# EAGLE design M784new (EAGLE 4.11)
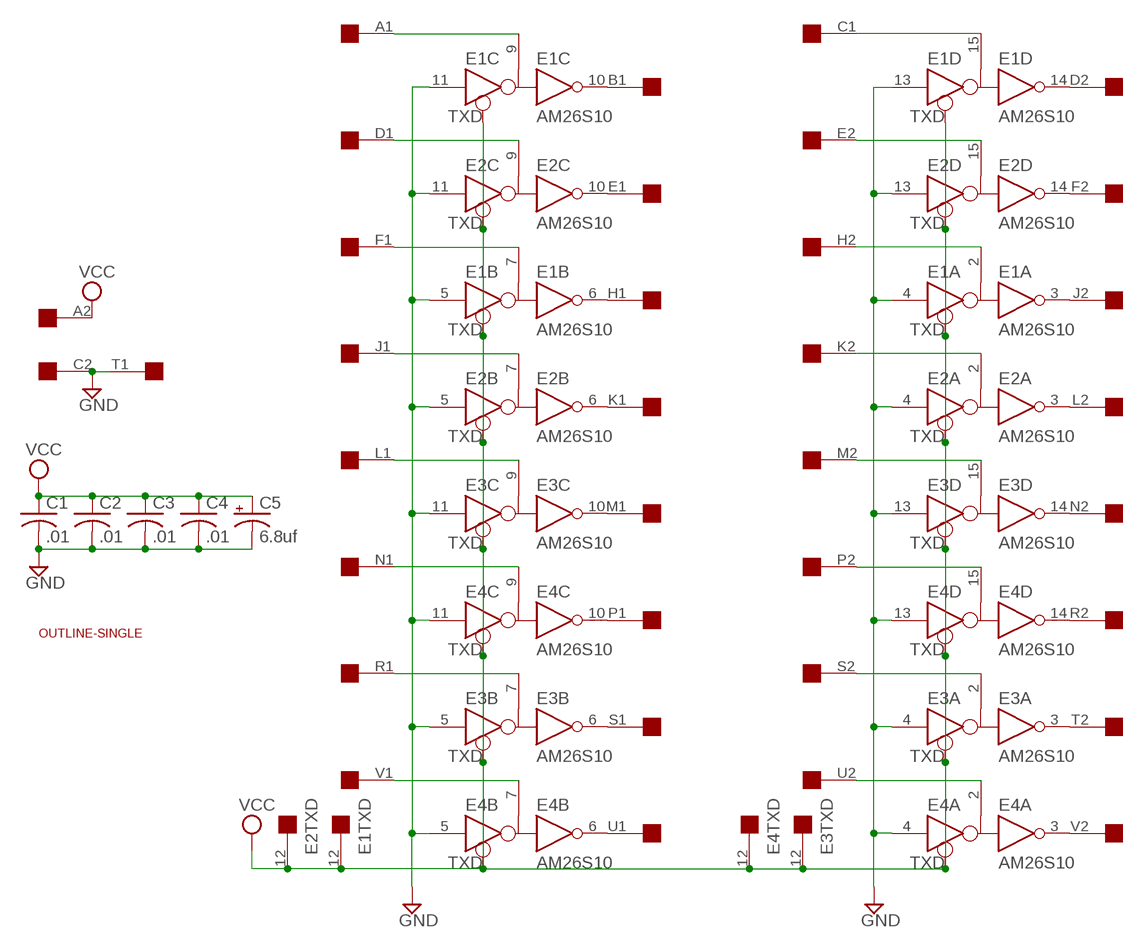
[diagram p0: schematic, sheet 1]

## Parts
C1  .01  C-US050-025X075  [C050-025X075]
C2  .01  C-US050-025X075  [C050-025X075]
C3  .01  C-US050-025X075  [C050-025X075]
C4  .01  C-US050-025X075  [C050-025X075]
C5  6.8uf  CPOL-USE15-5AXIAL  [E15-5]
E1  AM26S10  [DIL16]
E2  AM26S10  [DIL16]
E3  AM26S10  [DIL16]
E4  AM26S10  [DIL16]
U$1  SINGLE  [EDGE-CON2]
U$2  OUTLINE-SINGLE  [SINGLE]

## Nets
GND: C1.2 C2.2 C3.2 C4.2 C5.- E1.4(A:D) E1.5(B:D) E1.11(C:D) E1.13(D:D) E2.4(A:D) E2.5(B:D) E2.11(C:D) E2.13(D:D) E3.4(A:D) E3.5(B:D) E3.11(C:D) E3.13(D:D) E4.4(A:D) E4.5(B:D) E4.11(C:D) E4.13(D:D) U$1.C2 U$1.T1
N$1: E3.10(C:R) U$1.M1
N$2: E3.9(C:B) U$1.L1
N$3: E2.15(D:B) U$1.E2
N$4: E1.14(D:R) U$1.D2
N$5: E4.9(C:B) U$1.N1
N$6: E1.10(C:R) U$1.B1
N$7: E2.2(A:B) U$1.K2
N$8: E2.10(C:R) U$1.E1
N$9: E2.7(B:B) U$1.J1
N$10: E4.10(C:R) U$1.P1
N$11: E1.6(B:R) U$1.H1
N$12: E4.7(B:B) U$1.V1
N$13: E3.6(B:R) U$1.S1
N$14: E2.14(D:R) U$1.F2
N$15: E3.7(B:B) U$1.R1
N$16: E4.6(B:R) U$1.U1
N$17: E1.15(D:B) U$1.C1
N$18: E1.3(A:R) U$1.J2
N$19: E2.3(A:R) U$1.L2
N$20: E1.2(A:B) U$1.H2
N$21: E3.14(D:R) U$1.N2
N$22: E4.14(D:R) U$1.R2
N$23: E3.3(A:R) U$1.T2
N$24: E4.3(A:R) U$1.V2
N$25: E2.6(B:R) U$1.K1
N$26: E3.15(D:B) U$1.M2
N$27: E4.15(D:B) U$1.P2
N$28: E1.7(B:B) U$1.F1
N$29: E3.2(A:B) U$1.S2
N$30: E2.9(C:B) U$1.D1
N$31: E4.2(A:B) U$1.U2
N$32: E1.9(C:B) U$1.A1
VCC: C1.1 C2.1 C3.1 C4.1 C5.+ E1.12(TXD:TXD) E2.12(TXD:TXD) E3.12(TXD:TXD) E4.12(TXD:TXD) U$1.A2
Unconnected: U$1.B2

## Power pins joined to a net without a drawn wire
GND: E1.1(GND:GND) E1.8(PWR:GND) E2.1(GND:GND) E2.8(PWR:GND) E3.1(GND:GND) E3.8(PWR:GND) E4.1(GND:GND) E4.8(PWR:GND)
VCC: E1.16(PWR:VCC) E2.16(PWR:VCC) E3.16(PWR:VCC) E4.16(PWR:VCC)

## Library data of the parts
C1-C4 = rcl:C-US: CAPACITOR, American symbol
C5 = rcl:CPOL-US: POLARIZED CAPACITOR, American symbol
E1-E4 = dec-con:AM26S10: Bus Transceiver
U$1 = dec-con:SINGLE: Single-Height DEC board
U$2 = dec-con:OUTLINE-*: Board outlines for DEC boards.

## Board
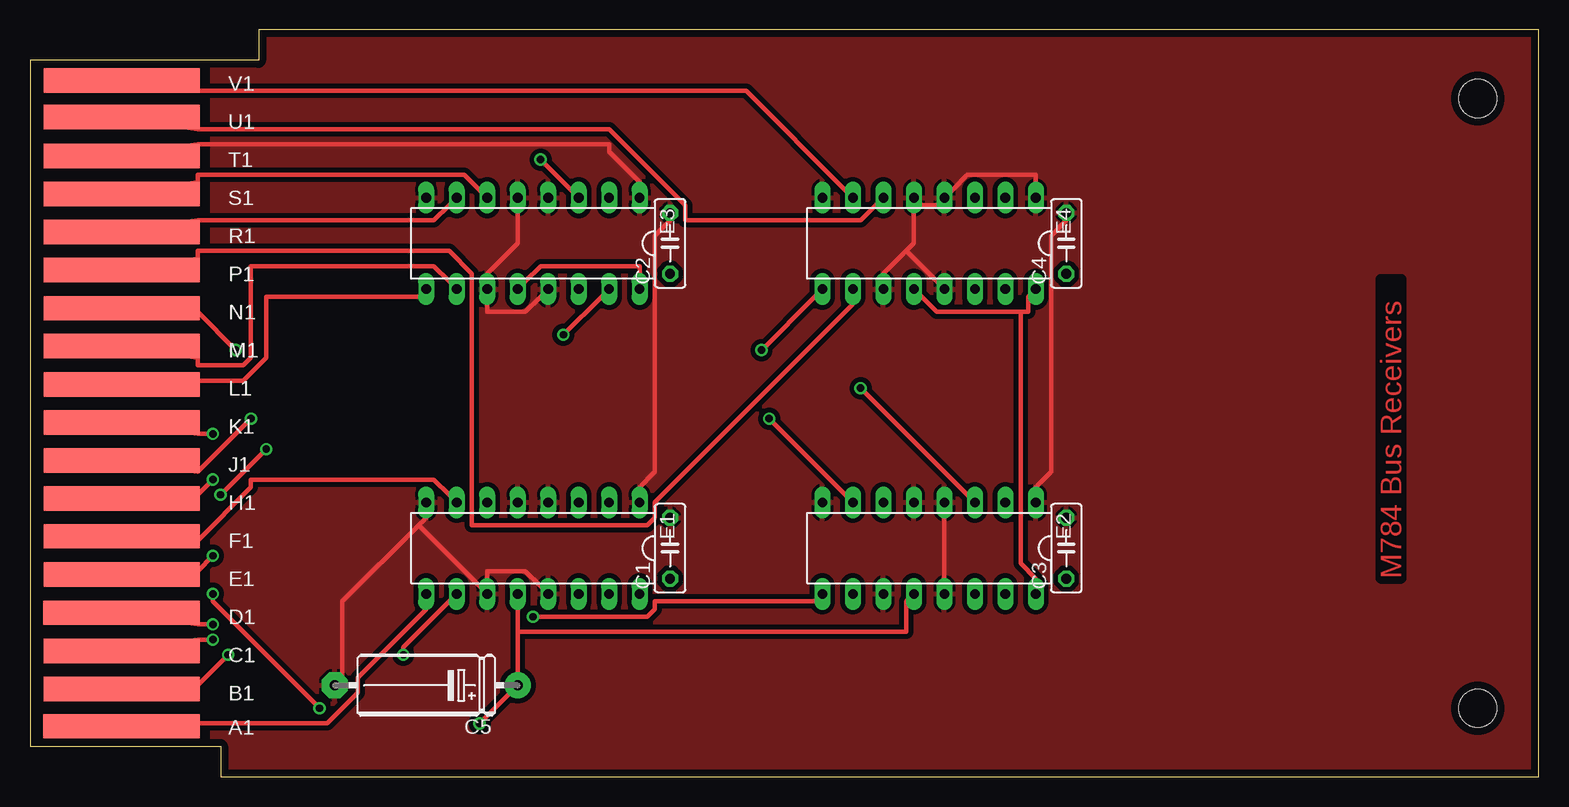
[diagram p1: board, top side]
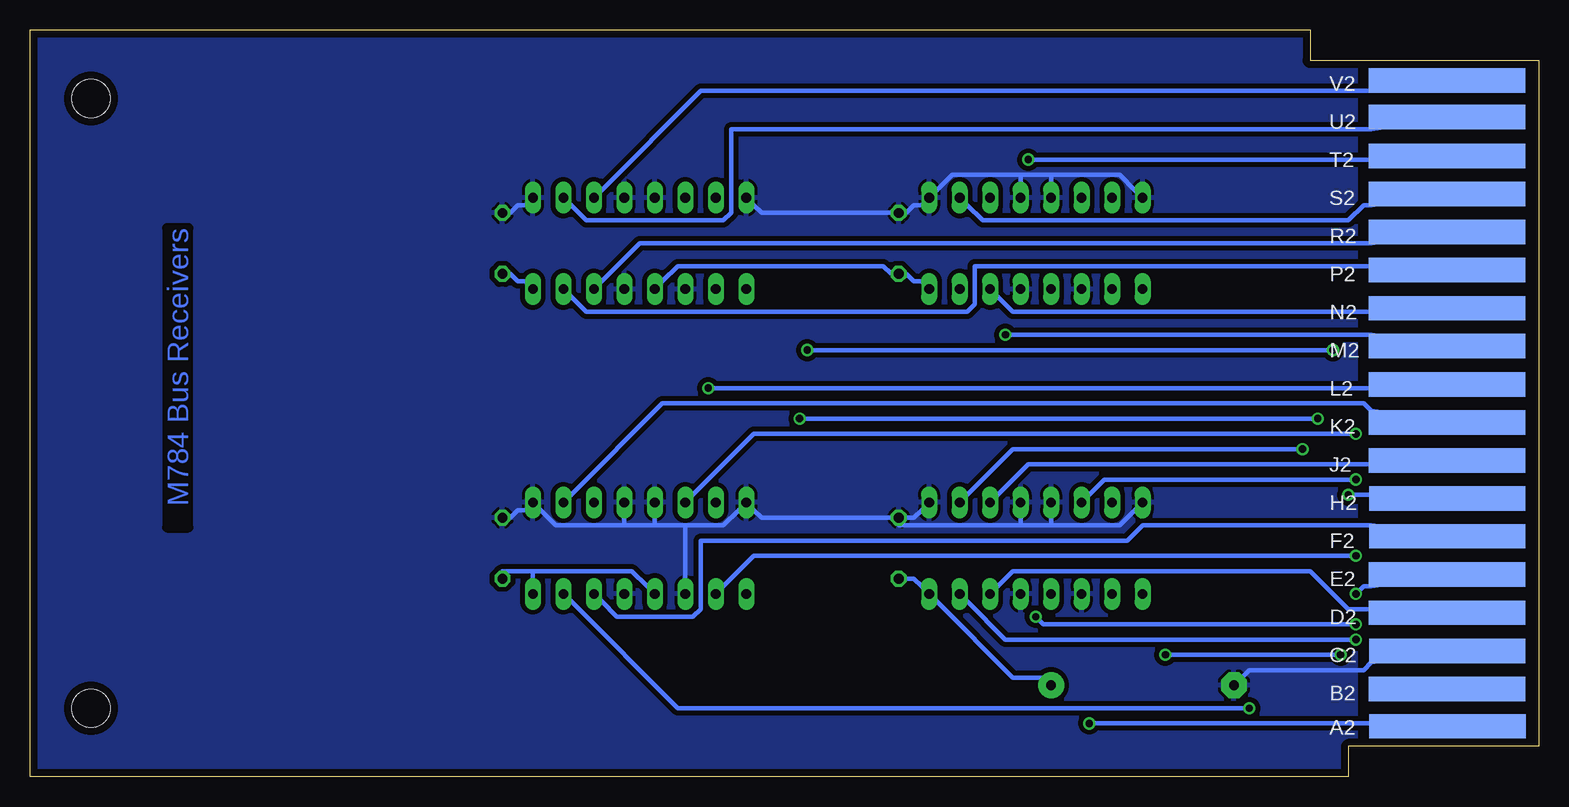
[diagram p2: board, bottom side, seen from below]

Size 125.73 x 62.23 mm. Coordinates in mm from the lower left corner, seen from the top.
Copper layers (1*16): Top 0.035mm / dielectric 1.5mm / Bottom 0.035mm
Design rules "15mils": minimum track width 15mil, minimum drill 24mil, track to track 15mil, track to pad 10mil, pad to pad 10mil, via to via 10mil, smd to smd 10mil, copper to edge 25mil, drill to drill 10mil, minimum pad ring 10mil, minimum via ring 8mil, stop-mask expansion 0mil, vias tented up to drill 0mil, thermal gap 10mil

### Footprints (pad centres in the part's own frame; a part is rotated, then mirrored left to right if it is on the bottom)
C050-025X075 = drill 0.813 octagon: 1 -2.54,0; 2 2.54,0
E15-5 = drill 0.813 pad 2.159 round: + -7.62,0 | drill 0.813 pad 2.159 octagon: - 7.62,0
DIL16 = drill 0.813 long: 1 -8.89,-3.81; 2 -6.35,-3.81; 3 -3.81,-3.81; 4 -1.27,-3.81; 5 1.27,-3.81; 6 3.81,-3.81; 7 6.35,-3.81; 8 8.89,-3.81; 9 8.89,3.81; 10 6.35,3.81; 11 3.81,3.81; 12 1.27,3.81; 13 -1.27,3.81; 14 -3.81,3.81; 15 -6.35,3.81; 16 -8.89,3.81
EDGE-CON2 = smd 13.017 x 2.032: A1 7.633,4.207; B1 7.639,7.327; C1 7.636,10.489; D1 7.633,13.665; E1 7.642,16.84; F1 7.642,20.041; H1 7.642,23.19; J1 7.642,26.34; K1 7.642,29.515; L1 7.642,32.69; M1 7.642,35.89; N1 7.642,39.04; P1 7.642,42.24; R1 7.642,45.39; S1 7.642,48.565; T1 7.642,51.74; U1 7.642,54.966; V1 7.642,58.026 | smd 13.017 x 2.032 bottom: A2 7.614,4.207; B2 7.642,7.328; C2 7.617,10.49; D2 7.642,13.665; E2 7.642,16.84; F2 7.617,20.041; H2 7.617,23.19; J2 7.642,26.34; K2 7.642,29.515; L2 7.642,32.69; M2 7.642,35.89; N2 7.642,39.04; P2 7.642,42.24; R2 7.642,45.39; S2 7.642,48.565; T2 7.642,51.74; U2 7.642,54.966; V2 7.642,58.026
SINGLE = hole 3.175: 120.65,56.515; 120.65,5.715

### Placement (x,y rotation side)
C1  53.34,19.05 90 top
C2  53.34,44.45 90 top
C3  86.36,19.05 90 top
C4  86.36,44.45 90 top
C5  33.02,7.62 180 top
E1  41.91,19.05 180 top
E2  74.93,19.05 180 top
E3  41.91,44.45 180 top
E4  74.93,44.45 180 top
U$1  0,0 0 top
U$2  0,0 0 top

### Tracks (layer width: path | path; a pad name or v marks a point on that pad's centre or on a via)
GND
  Top 0.381: U$1.T1 13.97,52.7 48.26,52.7 48.26,52.07 50.8,49.53 E3.1 | 32.39,20.95 26.04,14.61 26.04,8.26 C5.- | 32.39,20.95 33.02,21.59 E1.8 | C4.2 86.36,46.35 85.09,45.09 85.09,25.4 83.82,24.13 E2.1 | C2.2 53.34,46.35 52.07,45.09 52.07,25.4 50.8,24.13 E1.1 | E3.5 40.64,46.99 40.64,44.45 38.1,41.91 E3.11 38.1,39.37 38.1,38.73 41.28,38.73 42.55,40.01 E3.13 | 73.03,43.81 73.66,44.45 73.66,46.99 E4.5 74.3,47.62 75.57,47.62 E4.4 76.84,48.9 78.11,50.16 83.82,50.16 83.82,49.53 E4.1 | 73.03,43.81 71.12,41.91 E4.11 | 73.03,43.81 75.57,41.27 E4.13 | E2.13 76.2,16.51 76.2,21.59 E2.4 | 32.39,20.95 37.47,15.88 E1.11 38.1,16.51 38.1,17.14 41.28,17.14 42.55,15.88 E1.13
  Bottom 0.381: 43.18,50.16 48.9,50.16 50.17,48.9 E3.1 51.44,47.62 52.07,47.62 52.71,46.99 C2.2 53.98,46.99 64.77,46.99 65.41,47.62 E4.8 | 43.18,50.16 40.64,50.16 | 40.64,50.16 34.93,50.16 33.66,48.9 E3.8 | C5.- 24.77,8.26 24.13,8.89 14.61,8.89 13.97,9.53 U$1.C2 | C4.2 85.73,46.99 85.09,47.62 84.46,47.62 E4.1 | C3.2 85.73,21.59 85.09,22.23 84.46,22.23 E2.1 83.19,22.23 81.92,20.95 76.2,20.95 | E1.1 51.44,22.23 52.07,21.59 52.71,21.59 C1.2 | C1.2 53.98,21.59 64.77,21.59 65.41,22.23 E2.8 66.68,22.23 67.95,20.95 71.12,20.95 | 71.12,20.95 73.66,20.95 | 73.66,20.95 76.2,20.95 | 40.64,20.95 34.93,20.95 33.66,22.23 E1.8 | 40.64,20.95 43.18,20.95 | 43.18,20.95 53.34,20.95 C1.2 | 71.12,20.95 71.12,16.51 E2.11 | 40.64,20.95 40.64,21.59 E1.5 | 43.18,20.95 43.18,21.59 E1.4 | 73.66,20.95 73.66,21.59 E2.5 | 43.18,50.16 43.18,49.53 E3.4 | 76.2,20.95 76.2,21.59 E2.4 | 40.64,50.16 40.64,49.53 E3.5
  pour Top (isolate 0.406): 15.24,62.23 125.73,62.23 125.73,0 15.24,0
  pour Bottom (isolate 0.406): 15.24,62.23 125.73,62.23 125.73,0 15.24,0
N$1
  Top 0.381: E3.10 34.93,41.27 33.66,42.55 18.42,42.55 18.42,34.92 17.78,34.29 13.97,34.29 13.97,34.92 U$1.M1
N$2
  Top 0.381: E3.9 32.39,40.01 19.69,40.01 19.69,34.92 17.78,33.02 13.97,33.02 U$1.L1
N$3  (via drill 0.61)
  Top 0.381: v24.13,5.71 15.24,14.61 v15.24,15.24
  Bottom 0.381: v24.13,5.71 71.76,5.71 80.65,14.61 E2.15 | v15.24,15.24 14.61,15.88 13.97,15.88 U$1.E2
N$4
  Bottom 0.381: E1.14 45.09,15.88 43.82,17.14 19.05,17.14 15.88,13.97 13.97,13.97 U$1.D2
N$5  (via drill 0.61)
  Top 0.381: v60.96,35.56 65.41,40.01 E4.9 | v17.15,35.56 13.97,38.73 U$1.N1
  Bottom 0.381: v17.15,35.56 v60.96,35.56
N$6  (via drill 0.61)
  Top 0.381: v31.12,10.16 31.12,10.79 34.93,14.61 E1.10 | v16.51,10.16 13.97,7.62 U$1.B1
  Bottom 0.381: v16.51,10.16 v31.12,10.16
N$7
  Bottom 0.381: E2.2 80.65,23.5 73.03,31.11 14.61,31.11 13.97,30.48 U$1.K2
N$8  (via drill 0.61)
  Top 0.381: v15.24,18.41 13.97,17.14 U$1.E1
  Bottom 0.381: v15.24,18.41 65.41,18.41 67.95,15.88 E2.10
N$9  (via drill 0.61)
  Top 0.381: v61.6,29.84 67.95,23.5 E2.7 | v18.42,29.84 13.97,25.4 U$1.J1
  Bottom 0.381: v18.42,29.84 v61.6,29.84
N$10
  Top 0.381: E4.10 68.58,39.37 52.07,22.86 52.07,21.59 51.44,20.95 36.83,20.95 36.83,41.91 34.93,43.81 13.97,43.81 13.97,43.18 U$1.P1
N$11  (via drill 0.61)
  Top 0.381: v15.24,24.77 13.97,23.5 U$1.H1
  Bottom 0.381: v15.24,24.77 36.2,24.77 37.47,23.5 E1.6
N$12
  Top 0.381: E4.7 67.95,48.9 59.69,57.15 13.97,57.15 U$1.V1
N$13
  Top 0.381: E3.6 37.47,48.9 36.2,50.16 13.97,50.16 13.97,49.53 U$1.S1
N$14
  Bottom 0.381: E2.14 78.11,14.61 76.84,13.34 70.49,13.34 69.85,13.97 69.85,19.68 34.29,19.68 33.02,20.95 13.97,20.95 U$1.F2
N$15
  Top 0.381: E3.7 34.93,47.62 33.66,46.35 13.97,46.35 U$1.R1
N$16
  Top 0.381: E4.6 70.49,47.62 69.22,46.35 54.61,46.35 54.61,47.62 48.26,53.98 13.97,53.98 U$1.U1
N$17  (via drill 0.61)
  Top 0.381: v15.24,11.43 13.97,11.43 U$1.C1
  Bottom 0.381: v15.24,11.43 44.45,11.43 47.63,14.61 E1.15
N$18
  Bottom 0.381: E1.3 45.09,23.5 42.55,26.04 13.97,26.04 U$1.J2
N$19  (via drill 0.61)
  Top 0.381: v69.22,32.38 78.11,23.5 E2.3
  Bottom 0.381: v69.22,32.38 13.97,32.38 U$1.L2
N$20  (via drill 0.61)
  Top 0.381: v15.88,23.5 v19.69,27.3
  Bottom 0.381: v19.69,27.3 43.82,27.3 47.63,23.5 E1.2 | v15.88,23.5 13.97,23.5 U$1.H2
N$21
  Bottom 0.381: E3.14 45.09,40.01 43.82,38.73 13.97,38.73 U$1.N2
N$22
  Bottom 0.381: E4.14 78.11,41.27 74.93,44.45 13.97,44.45 U$1.R2
N$23  (via drill 0.61)
  Top 0.381: v42.55,51.44 45.09,48.9 E3.3
  Bottom 0.381: v42.55,51.44 13.97,51.44 U$1.T2
N$24
  Bottom 0.381: E4.3 78.11,48.9 69.85,57.15 13.97,57.15 U$1.V2
N$25  (via drill 0.61)
  Top 0.381: v15.24,28.57 13.97,28.57 U$1.K1
  Bottom 0.381: v15.24,28.57 65.41,28.57 70.49,23.5 E2.6
N$26  (via drill 0.61)
  Top 0.381: v44.45,36.83 47.63,40.01 E3.15
  Bottom 0.381: v44.45,36.83 13.97,36.83 U$1.M2
N$27
  Bottom 0.381: E4.15 80.65,40.01 79.38,38.73 47.63,38.73 46.99,39.37 46.99,42.55 13.97,42.55 U$1.P2
N$28
  Top 0.381: E1.7 34.93,23.5 33.66,24.77 18.42,24.77 18.42,24.13 13.97,19.68 U$1.F1
N$29
  Bottom 0.381: E3.2 47.63,47.62 46.36,46.35 15.88,46.35 14.61,47.62 13.97,47.62 U$1.S2
N$30  (via drill 0.61)
  Top 0.381: v41.91,13.34 51.44,13.34 52.07,13.97 52.07,14.61 65.41,14.61 E2.9 | v15.24,12.7 13.97,12.7 U$1.D1
  Bottom 0.381: v41.91,13.34 41.28,12.7 v15.24,12.7
N$31
  Bottom 0.381: E4.2 80.65,47.62 79.38,46.35 67.95,46.35 67.31,46.99 67.31,53.98 13.97,53.98 U$1.U2
N$32
  Top 0.381: E1.9 33.02,13.97 27.31,8.26 27.31,6.99 24.77,4.45 13.97,4.45 U$1.A1
VCC  (via drill 0.61)
  Top 0.381: 40.64,12.06 40.64,8.26 C5.+ 40.01,6.99 v37.47,4.45 | 40.64,12.06 40.64,13.97 E1.12 | E3.12 41.28,41.27 42.55,42.55 50.8,42.55 50.8,41.91 E3.16 | 82.55,38.73 83.19,38.73 83.19,40.01 E4.16 | 82.55,38.73 75.57,38.73 74.3,40.01 E4.12 | 82.55,38.73 82.55,17.78 83.82,16.51 E2.16 | 40.64,12.06 73.03,12.06 73.03,14.61 E2.12
  Bottom 0.381: C1.1 52.71,16.51 52.07,16.51 51.44,15.88 E1.16 50.17,14.61 43.82,8.26 41.28,8.26 C5.+ | E3.16 51.44,41.27 52.07,41.27 52.71,41.91 C2.1 53.98,41.91 54.61,42.55 71.76,42.55 73.03,41.27 E4.12 | 83.82,17.14 86.36,17.14 C3.1 | 83.82,17.14 75.57,17.14 74.3,15.88 E2.12 | 83.82,17.14 83.82,16.51 E2.16 | C4.1 85.73,41.91 85.09,41.27 84.46,41.27 E4.16 | v37.47,4.45 13.97,4.45 U$1.A2

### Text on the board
Top: M784 Bus Receivers
Bottom: M784 Bus Receivers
